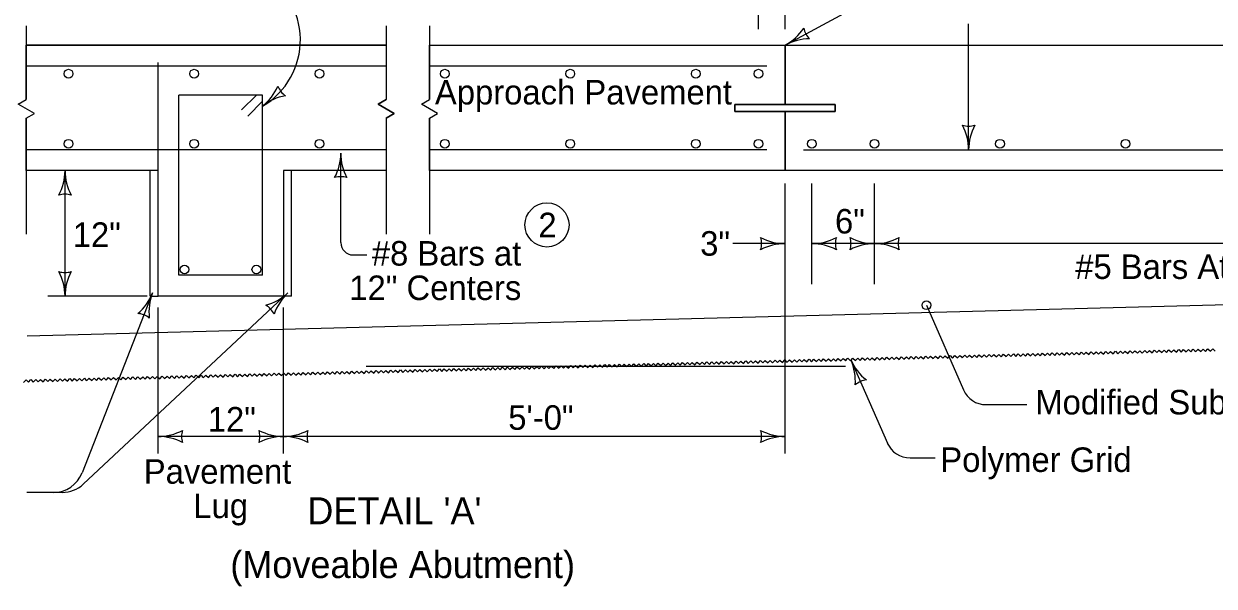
# Model space of a CAD drawing. Extents: x 8925 to 81668, y 4369 to 11918.
# Drawn here: x 11330 to 12301, y 9119 to 9577 of the extents above; entities that cross this region are included whole.
import ezdxf

# ---------------------------------------------------------------- set-up
doc = ezdxf.new("R2010")
doc.units = 0
for name, color, linetype in [('dsnShtPlotShapeBatchPrint', 7, 'Continuous'), ('dsnStdBorder', 7, 'Continuous'), ('Level 2', 7, 'Continuous'), ('Level 3', 7, 'Continuous'), ('Level 5', 7, 'Continuous')]:
    doc.layers.add(name, color=color, linetype=linetype)

msp = doc.modelspace()

# ---------------------------------------------------------------- linework, layer by layer
at = {"layer": 'dsnShtPlotShapeBatchPrint'}
for p, q in [((11950.96, 9572.8), (11950.96, 9732.01)), ((11950.96, 9559.76), (12114.15, 9648.09)), ((11929.18, 9572.8), (11929.18, 9623.99)), ((12100.63, 9474.5), (12100.63, 9577.16)), ((12100.63, 9474.5), (12100.63, 9577.16)), ((11331.99, 9515.32), (11331.99, 9559.76)), ((11331.99, 9559.76), (11625.42, 9559.76)), ((11625.42, 9559.76), (11625.42, 9515.32)), ((11660.94, 9515.32), (11660.94, 9559.76)), ((11660.94, 9559.76), (11950.96, 9559.76)), ((11660.94, 9559.76), (11950.96, 9559.76)), ((11950.96, 9559.76), (11950.96, 9511.44)), ((11950.96, 9511.44), (11950.96, 9559.76)), ((11950.96, 9559.76), (12427.36, 9559.76)), ((11950.96, 9559.76), (12427.36, 9559.76)), ((11950.96, 9511.44), (11950.96, 9559.76)), ((11439.44, 9382.79), (11439.44, 9545.73)), ((11660.94, 9515.32), (11660.94, 9515.32)), ((11950.96, 9511.44), (11910.04, 9511.45)), ((11910.04, 9511.45), (11910.04, 9505.76)), ((11910.04, 9511.45), (11910.04, 9505.77)), ((11910.04, 9505.77), (11950.96, 9505.76)), ((11991.89, 9505.76), (11910.04, 9505.76)), ((11991.88, 9511.45), (11950.96, 9511.44)), ((11950.96, 9505.76), (11991.88, 9505.77)), ((11950.96, 9505.76), (11950.96, 9457.45)), ((11950.96, 9457.45), (11950.96, 9505.76)), ((11950.96, 9457.45), (11950.96, 9505.76)), ((11991.88, 9505.77), (11991.88, 9511.45)), ((11991.89, 9505.76), (11991.89, 9511.45)), ((11331.99, 9457.45), (11331.99, 9500.16)), ((11625.42, 9500.15), (11625.42, 9457.45)), ((11660.94, 9457.45), (11660.94, 9500.15)), ((11588.49, 9398.83), (11588.49, 9471.72)), ((11439.44, 9457.45), (11331.99, 9457.45)), ((11363.58, 9355.15), (11363.58, 9457.45)), ((11439.44, 9355.15), (11439.44, 9457.45)), ((11541.74, 9457.46), (11541.74, 9355.15)), ((11625.42, 9457.45), (11541.74, 9457.45)), ((11541.74, 9457.45), (11541.74, 9355.15)), ((11950.96, 9457.45), (11660.94, 9457.45)), ((11950.96, 9457.45), (11660.94, 9457.45)), ((12427.36, 9457.45), (11950.96, 9457.45)), ((12427.36, 9457.45), (11950.96, 9457.45)), ((11950.96, 9226.93), (11950.96, 9446.96)), ((11972.75, 9364.95), (11972.75, 9446.96)), ((12023.9, 9364.95), (12023.9, 9446.96)), ((11950.96, 9397.95), (11908.33, 9397.95)), ((12023.9, 9397.95), (11972.75, 9397.95)), ((12846.66, 9397.95), (12023.9, 9397.95)), ((11598.59, 9388.72), (11609.85, 9388.72)), ((11332.73, 9322.65), (12427.72, 9351.24)), ((11430.46, 9355.15), (11349.66, 9355.15)), ((11434.98, 9357.74), (11377.44, 9210.94)), ((11545.34, 9357.74), (11378.42, 9201.79)), ((11541.74, 9355.15), (11439.44, 9355.15)), ((11439.44, 9226.93), (11439.44, 9345.73)), ((11541.74, 9226.93), (11541.74, 9345.73)), ((12066.16, 9347.65), (12096.31, 9278.76)), ((12004.65, 9303.08), (12034.31, 9235.33)), ((12114.83, 9266.66), (12148.21, 9266.66)), ((11541.74, 9240.71), (11439.44, 9240.71)), ((11950.96, 9240.71), (11541.74, 9240.71)), ((12052.82, 9223.23), (12073.33, 9223.23)), ((11361.35, 9195.06), (11332.39, 9195.06))]:
    msp.add_line(p, q, dxfattribs=at)
for points in [[(11331.99, 9500.16), (11338.56, 9503.94), (11325.42, 9511.53), (11331.99, 9515.32)], [(11625.42, 9515.32), (11618.86, 9511.53), (11631.99, 9503.94), (11625.42, 9500.16)], [(11660.94, 9500.16), (11667.51, 9503.94), (11654.37, 9511.53), (11660.94, 9515.32)], [(12237.29, 9309.59), (12238.31, 9308.62), (12240.24, 9310.66), (12242.28, 9308.73), (12244.21, 9310.76), (12246.24, 9308.83), (12248.18, 9310.87), (12250.21, 9308.94), (12252.15, 9310.97), (12254.18, 9309.04), (12256.11, 9311.07), (12258.15, 9309.14), (12260.08, 9311.18), (12262.11, 9309.24), (12264.05, 9311.28), (12266.08, 9309.35), (12268.01, 9311.39), (12270.05, 9309.45), (12271.98, 9311.49), (12274.02, 9309.56), (12275.95, 9311.59), (12277.98, 9309.66), (12279.92, 9311.69), (12281.95, 9309.77), (12283.88, 9311.8), (12284.9, 9310.83)], [(12284.9, 9310.83), (12285.92, 9309.87), (12287.85, 9311.9), (12289.89, 9309.97), (12291.82, 9312.01), (12293.86, 9310.08), (12295.79, 9312.11), (12297.82, 9310.18), (12299.75, 9312.21), (12301.79, 9310.28)], [(11856.43, 9299.64), (11857.44, 9298.68), (11859.38, 9300.71), (11861.41, 9298.78), (11863.34, 9300.82), (11865.38, 9298.88), (11867.31, 9300.92), (11869.35, 9298.99), (11871.28, 9301.02), (11873.32, 9299.09), (11875.24, 9301.13), (11877.28, 9299.2), (11879.21, 9301.23), (11881.25, 9299.3), (11883.18, 9301.33), (11885.22, 9299.41), (11887.15, 9301.44), (11889.18, 9299.51), (11891.11, 9301.54), (11893.15, 9299.61), (11895.08, 9301.64), (11897.12, 9299.71), (11899.05, 9301.75), (11901.09, 9299.82), (11903.02, 9301.85), (11904.04, 9300.89)], [(11904.04, 9300.89), (11905.05, 9299.92), (11906.99, 9301.96), (11909.02, 9300.02), (11910.95, 9302.06), (11912.98, 9300.13), (11914.92, 9302.16), (11916.95, 9300.23), (11918.89, 9302.27), (11920.92, 9300.34), (11922.85, 9302.37), (11924.89, 9300.44), (11926.82, 9302.47), (11928.86, 9300.55), (11930.79, 9302.58), (11932.82, 9300.65), (11934.75, 9302.68), (11936.79, 9300.75), (11938.72, 9302.78), (11940.76, 9300.85), (11942.69, 9302.89), (11944.73, 9300.96), (11946.66, 9302.99), (11948.69, 9301.06), (11950.63, 9303.09), (11951.64, 9302.13)], [(11951.64, 9302.13), (11952.66, 9301.16), (11954.59, 9303.2), (11956.63, 9301.27), (11958.56, 9303.3), (11960.6, 9301.37), (11962.53, 9303.41), (11964.56, 9301.48), (11966.5, 9303.51), (11968.53, 9301.58), (11970.46, 9303.61), (11972.5, 9301.68), (11974.43, 9303.72), (11976.46, 9301.79), (11978.4, 9303.82), (11980.43, 9301.89), (11982.36, 9303.92), (11984.4, 9301.99), (11986.33, 9304.03), (11988.37, 9302.1), (11990.3, 9304.13), (11992.33, 9302.2), (11994.27, 9304.23), (11996.3, 9302.3), (11998.23, 9304.34), (11999.25, 9303.38)], [(11999.25, 9303.38), (12000.27, 9302.41), (12002.2, 9304.44), (12004.24, 9302.51), (12006.17, 9304.55), (12008.21, 9302.62), (12010.14, 9304.65), (12012.17, 9302.72), (12014.1, 9304.75), (12016.14, 9302.82), (12018.07, 9304.85), (12020.11, 9302.93), (12022.04, 9304.96), (12024.07, 9303.03), (12026.01, 9305.06), (12028.04, 9303.13), (12029.97, 9305.16), (12032.01, 9303.24), (12033.94, 9305.27), (12035.98, 9303.34), (12037.91, 9305.37), (12039.94, 9303.44), (12041.87, 9305.48), (12043.91, 9303.54), (12045.84, 9305.58), (12046.86, 9304.61)], [(12046.86, 9304.61), (12047.88, 9303.65), (12049.81, 9305.69), (12051.84, 9303.75), (12053.78, 9305.79), (12055.81, 9303.86), (12057.74, 9305.89), (12059.78, 9303.96), (12061.71, 9305.99), (12063.75, 9304.07), (12065.68, 9306.1), (12067.72, 9304.17), (12069.65, 9306.2), (12071.68, 9304.27), (12073.62, 9306.3), (12075.65, 9304.38), (12077.58, 9306.41), (12079.62, 9304.48), (12081.55, 9306.51), (12083.58, 9304.58), (12085.52, 9306.62), (12087.55, 9304.68), (12089.48, 9306.72), (12091.52, 9304.79), (12093.45, 9306.83), (12094.47, 9305.86)], [(12094.47, 9305.86), (12095.48, 9304.89), (12097.42, 9306.93), (12099.45, 9305), (12101.38, 9307.03), (12103.42, 9305.1), (12105.35, 9307.13), (12107.38, 9305.2), (12109.32, 9307.24), (12111.36, 9305.31), (12113.29, 9307.34), (12115.32, 9305.41), (12117.25, 9307.45), (12119.29, 9305.52), (12121.22, 9307.55), (12123.26, 9305.62), (12125.19, 9307.65), (12127.23, 9305.72), (12129.16, 9307.76), (12131.19, 9305.82), (12133.13, 9307.86), (12135.16, 9305.93), (12137.09, 9307.97), (12139.12, 9306.03), (12141.06, 9308.07), (12142.07, 9307.1)], [(12142.07, 9307.1), (12143.09, 9306.14), (12145.03, 9308.17), (12147.06, 9306.24), (12148.99, 9308.27), (12151.03, 9306.34), (12152.96, 9308.38), (12155, 9306.45), (12156.93, 9308.48), (12158.96, 9306.55), (12160.9, 9308.59), (12162.93, 9306.66), (12164.86, 9308.68), (12166.9, 9306.76), (12168.83, 9308.79), (12170.87, 9306.86), (12172.79, 9308.9), (12174.83, 9306.96), (12176.76, 9309), (12178.8, 9307.07), (12180.73, 9309.11), (12182.77, 9307.17), (12184.7, 9309.21), (12186.74, 9307.28), (12188.67, 9309.31), (12189.69, 9308.35)], [(12189.69, 9308.35), (12190.7, 9307.38), (12192.64, 9309.41), (12194.67, 9307.48), (12196.6, 9309.52), (12198.64, 9307.59), (12200.57, 9309.62), (12202.6, 9307.69), (12204.53, 9309.73), (12206.57, 9307.8), (12208.5, 9309.83), (12210.54, 9307.9), (12212.47, 9309.93), (12214.51, 9308.01), (12216.44, 9310.04), (12218.47, 9308.1), (12220.4, 9310.14), (12222.44, 9308.21), (12224.37, 9310.25), (12226.41, 9308.31), (12228.34, 9310.35), (12230.38, 9308.42), (12232.31, 9310.45), (12234.34, 9308.52), (12236.28, 9310.55), (12237.29, 9309.59)], [(11523.17, 9290.94), (11524.19, 9289.97), (11526.11, 9292.01), (11528.15, 9290.08), (11530.09, 9292.11), (11532.12, 9290.18), (11534.05, 9292.22), (11536.09, 9290.29), (11538.02, 9292.32), (11540.05, 9290.39), (11541.99, 9292.42), (11544.02, 9290.49), (11545.96, 9292.53), (11547.99, 9290.6), (11549.92, 9292.63), (11551.96, 9290.7), (11553.89, 9292.73), (11555.93, 9290.81), (11557.86, 9292.83), (11559.89, 9290.91), (11561.83, 9292.94), (11563.86, 9291.01), (11565.79, 9293.05), (11567.83, 9291.11), (11569.76, 9293.15), (11570.78, 9292.18)], [(11570.78, 9292.18), (11571.79, 9291.22), (11573.73, 9293.25), (11575.76, 9291.32), (11577.69, 9293.36), (11579.73, 9291.42), (11581.66, 9293.46), (11583.7, 9291.53), (11585.63, 9293.56), (11587.67, 9291.63), (11589.6, 9293.67), (11591.63, 9291.73), (11593.56, 9293.77), (11595.6, 9291.84), (11597.53, 9293.87), (11599.57, 9291.95), (11601.5, 9293.97), (11603.53, 9292.05), (11605.46, 9294.08), (11607.5, 9292.15), (11609.43, 9294.18), (11611.47, 9292.25), (11613.4, 9294.29), (11615.44, 9292.36), (11617.37, 9294.39), (11618.39, 9293.42)], [(11618.39, 9293.42), (11619.4, 9292.46), (11621.34, 9294.49), (11623.37, 9292.56), (11625.31, 9294.6), (11627.34, 9292.67), (11629.27, 9294.7), (11631.3, 9292.77), (11633.24, 9294.81), (11635.27, 9292.87), (11637.2, 9294.91), (11639.24, 9292.98), (11641.17, 9295.01), (11643.21, 9293.08), (11645.14, 9295.11), (11647.18, 9293.19), (11649.1, 9295.22), (11651.14, 9293.29), (11653.07, 9295.32), (11655.11, 9293.39), (11657.04, 9295.43), (11659.08, 9293.5), (11661.01, 9295.53), (11663.04, 9293.6), (11664.98, 9295.63), (11666, 9294.67)], [(11666, 9294.67), (11667.01, 9293.71), (11668.94, 9295.74), (11670.98, 9293.81), (11672.91, 9295.84), (11674.95, 9293.91), (11676.88, 9295.95), (11678.91, 9294.01), (11680.85, 9296.05), (11682.88, 9294.12), (11684.82, 9296.16), (11686.85, 9294.22), (11688.78, 9296.25), (11690.81, 9294.33), (11692.75, 9296.36), (11694.78, 9294.43), (11696.71, 9296.46), (11698.75, 9294.53), (11700.68, 9296.57), (11702.72, 9294.64), (11704.65, 9296.67), (11706.68, 9294.74), (11708.61, 9296.77), (11710.65, 9294.85), (11712.59, 9296.88), (11713.6, 9295.91)], [(11713.6, 9295.91), (11714.62, 9294.95), (11716.55, 9296.98), (11718.59, 9295.05), (11720.52, 9297.09), (11722.56, 9295.15), (11724.49, 9297.19), (11726.52, 9295.26), (11728.46, 9297.3), (11730.49, 9295.36), (11732.42, 9297.39), (11734.46, 9295.47), (11736.39, 9297.5), (11738.42, 9295.57), (11740.36, 9297.6), (11742.39, 9295.67), (11744.32, 9297.71), (11746.36, 9295.78), (11748.29, 9297.81), (11750.33, 9295.88), (11752.26, 9297.91), (11754.29, 9295.99), (11756.22, 9298.01), (11758.26, 9296.09), (11760.19, 9298.12), (11761.21, 9297.15)], [(11761.21, 9297.15), (11762.23, 9296.19), (11764.16, 9298.23), (11766.2, 9296.29), (11768.13, 9298.33), (11770.16, 9296.4), (11772.09, 9298.43), (11774.13, 9296.5), (11776.06, 9298.53), (11778.1, 9296.61), (11780.03, 9298.64), (11782.07, 9296.71), (11784, 9298.74), (11786.03, 9296.81), (11787.97, 9298.85), (11790, 9296.92), (11791.93, 9298.95), (11793.96, 9297.02), (11795.9, 9299.05), (11797.93, 9297.13), (11799.87, 9299.16), (11801.9, 9297.23), (11803.84, 9299.26), (11805.87, 9297.33), (11807.8, 9299.37), (11808.82, 9298.4)], [(11808.82, 9298.4), (11809.83, 9297.43), (11811.76, 9299.47), (11813.81, 9297.54), (11815.74, 9299.57), (11817.77, 9297.64), (11819.7, 9299.68), (11821.74, 9297.75), (11823.67, 9299.78), (11825.71, 9297.85), (11827.64, 9299.88), (11829.67, 9297.95), (11831.6, 9299.99), (11833.64, 9298.06), (11835.57, 9300.09), (11837.61, 9298.16), (11839.54, 9300.19), (11841.58, 9298.27), (11843.51, 9300.3), (11845.54, 9298.37), (11847.48, 9300.4), (11849.51, 9298.47), (11851.44, 9300.51), (11853.47, 9298.57), (11855.41, 9300.61), (11856.43, 9299.64)], [(11332.96, 9285.84), (11331.85, 9286.9), (11329.72, 9284.67)], [(11332.74, 9285.96), (11333.76, 9285), (11335.68, 9287.04), (11337.72, 9285.11), (11339.66, 9287.14), (11341.69, 9285.21), (11343.62, 9287.24), (11345.65, 9285.31), (11347.59, 9287.34), (11349.62, 9285.42), (11351.56, 9287.45), (11353.59, 9285.52), (11355.52, 9287.56), (11357.56, 9285.62), (11359.49, 9287.66), (11361.53, 9285.73), (11363.46, 9287.76), (11365.49, 9285.83), (11367.42, 9287.86), (11369.46, 9285.93), (11371.39, 9287.97), (11373.42, 9286.04), (11375.36, 9288.07), (11377.4, 9286.14), (11379.33, 9288.17), (11380.34, 9287.21)], [(11380.34, 9287.21), (11381.36, 9286.25), (11383.29, 9288.28), (11385.33, 9286.35), (11387.26, 9288.38), (11389.3, 9286.45), (11391.23, 9288.48), (11393.27, 9286.56), (11395.2, 9288.59), (11397.23, 9286.66), (11399.17, 9288.7), (11401.2, 9286.76), (11403.13, 9288.8), (11405.16, 9286.87), (11407.1, 9288.9), (11409.13, 9286.97), (11411.06, 9289), (11413.1, 9287.07), (11415.03, 9289.11), (11417.07, 9287.18), (11419, 9289.21), (11421.04, 9287.28), (11422.96, 9289.31), (11425, 9287.39), (11426.94, 9289.42), (11427.95, 9288.45)], [(11427.95, 9288.45), (11428.97, 9287.49), (11430.9, 9289.52), (11432.94, 9287.59), (11434.87, 9289.63), (11436.91, 9287.69), (11438.84, 9289.73), (11440.87, 9287.8), (11442.8, 9289.84), (11444.84, 9287.9), (11446.77, 9289.94), (11448.81, 9288.01), (11450.74, 9290.04), (11452.77, 9288.11), (11454.71, 9290.14), (11456.74, 9288.21), (11458.68, 9290.25), (11460.71, 9288.32), (11462.64, 9290.35), (11464.68, 9288.42), (11466.61, 9290.45), (11468.64, 9288.53), (11470.57, 9290.56), (11472.61, 9288.63), (11474.54, 9290.66), (11475.56, 9289.7)], [(11475.56, 9289.7), (11476.58, 9288.73), (11478.51, 9290.77), (11480.55, 9288.83), (11482.48, 9290.87), (11484.51, 9288.94), (11486.44, 9290.97), (11488.48, 9289.04), (11490.41, 9291.08), (11492.45, 9289.15), (11494.38, 9291.18), (11496.41, 9289.25), (11498.35, 9291.28), (11500.38, 9289.35), (11502.32, 9291.39), (11504.35, 9289.45), (11506.28, 9291.49), (11508.32, 9289.56), (11510.25, 9291.59), (11512.28, 9289.67), (11514.22, 9291.7), (11516.25, 9289.77), (11518.18, 9291.8), (11520.22, 9289.87), (11522.15, 9291.91), (11523.17, 9290.94)]]:
    msp.add_lwpolyline(points, dxfattribs=at)
for centre, radius, start, end in [((11492.57, 9564.1), 62.96, 300.6735, 60.83314), ((11598.59, 9398.83), 10.1, 180, 270), ((12114.83, 9286.86), 20.21, 203.64012, 270), ((12052.82, 9243.44), 20.21, 203.64012, 270)]:
    msp.add_arc(centre, radius, start, end, dxfattribs=at)
at = {"layer": 'dsnStdBorder'}
for p, q in [((11331.99, 9575.4), (11331.99, 9515.32)), ((11625.42, 9575.4), (11625.42, 9515.32)), ((11660.94, 9575.4), (11660.94, 9515.32)), ((11625.42, 9559.76), (11331.99, 9559.76)), ((11950.96, 9511.44), (11950.96, 9559.76)), ((11625.42, 9542.71), (11331.99, 9542.71)), ((11935.9, 9542.71), (11660.94, 9542.71)), ((11456.49, 9372.2), (11456.49, 9518.95)), ((11524.69, 9518.95), (11456.49, 9518.95)), ((11519.71, 9518.95), (11507.65, 9506.89)), ((11524.69, 9372.2), (11524.69, 9518.95)), ((11524.69, 9513.96), (11512.63, 9501.91)), ((11910.04, 9505.76), (11910.04, 9511.45)), ((11910.04, 9511.45), (11991.89, 9511.45)), ((11991.89, 9505.76), (11910.04, 9505.76)), ((11950.96, 9457.45), (11950.96, 9505.76)), ((11991.89, 9511.45), (11991.89, 9505.76)), ((11331.99, 9500.15), (11331.99, 9405.54)), ((11625.42, 9500.15), (11625.42, 9405.54)), ((11660.94, 9500.15), (11660.94, 9405.54)), ((11625.42, 9474.5), (11331.99, 9474.5)), ((11935.9, 9474.5), (11660.94, 9474.5)), ((11966.03, 9474.5), (12427.36, 9474.5)), ((11439.44, 9457.45), (11331.99, 9457.45)), ((11432.97, 9355.15), (11432.97, 9457.46)), ((11439.44, 9355.15), (11439.44, 9457.46)), ((11625.42, 9457.45), (11541.74, 9457.45)), ((11548.21, 9355.15), (11548.21, 9457.46)), ((11524.69, 9372.2), (11456.49, 9372.2)), ((11432.97, 9355.15), (11439.44, 9355.15)), ((11541.74, 9355.15), (11439.44, 9355.15)), ((11548.21, 9355.15), (11541.74, 9355.15)), ((11609.2, 9297.99), (12000.11, 9297.99))]:
    msp.add_line(p, q, dxfattribs=at)
for points in [[(11331.99, 9500.16), (11338.56, 9503.94), (11325.42, 9511.53), (11331.99, 9515.32)], [(11625.42, 9500.16), (11631.99, 9503.94), (11618.86, 9511.53), (11625.42, 9515.32)], [(11660.94, 9500.16), (11667.51, 9503.94), (11654.37, 9511.53), (11660.94, 9515.32)]]:
    msp.add_lwpolyline(points, dxfattribs=at)
msp.add_circle((11756.7, 9413.16), 18, dxfattribs=at)
for centre, radius, start, end in [((11498.13, 9543.14), 42.5, 308.6676, 336.74009), ((11552.51, 9532.22), 16.42, 200.93424, 236.40095), ((11551.24, 9476.77), 42.5, 100.59511, 128.6676), ((11354.16, 9220.06), 25, 270, 338.59752), ((11361.35, 9220.06), 25, 270, 313.05415)]:
    msp.add_arc(centre, radius, start, end, dxfattribs=at)
at = {"layer": 'Level 2'}
for centre in [(11366.5, 9536.5), (11468.81, 9536.5), (11571.11, 9536.5), (11673.42, 9536.5), (11775.72, 9536.5), (11878.03, 9536.5), (11929.18, 9536.5), (11366.5, 9479.4), (11468.81, 9479.4), (11571.11, 9479.4), (11673.42, 9479.4), (11775.72, 9479.4), (11878.03, 9479.4), (11929.18, 9479.4), (11972.75, 9479.4), (12023.9, 9479.4), (12126.2, 9479.4), (12228.51, 9479.4), (11461.09, 9376.82), (11519.63, 9376.82)]:
    msp.add_circle(centre, 3.55, dxfattribs=at)
at = {"layer": 'Level 3'}
for centre, radius, start, end in [((11930.73, 9597.13), 42.5, 298.42581, 326.4983), ((11982.3, 9576.72), 16.42, 190.69246, 226.15916), ((11971.19, 9522.38), 42.5, 90.35332, 118.42581), ((12100.63, 9510.14), 16.42, 252.26665, 287.73335), ((12058.13, 9474.5), 42.5, 360, 28.07249), ((12143.13, 9474.5), 42.5, 151.92751, 180), ((11545.99, 9471.72), 42.5, 331.92751, 360), ((11630.99, 9471.72), 42.5, 180, 208.07249), ((11321.08, 9457.45), 42.5, 331.92751, 360), ((11406.08, 9457.45), 42.5, 180, 208.07249), ((11588.49, 9436.08), 16.42, 72.26665, 107.73335), ((11363.58, 9421.82), 16.42, 72.26665, 107.73335), ((11915.33, 9397.95), 16.42, 342.26665, 17.73335), ((11950.96, 9440.45), 42.5, 241.92751, 270), ((11972.75, 9440.45), 42.5, 270, 298.07249), ((12008.38, 9397.95), 16.42, 162.26665, 197.73335), ((11988.26, 9397.95), 16.42, 342.26665, 17.73335), ((12023.9, 9440.45), 42.5, 241.92751, 270), ((12023.9, 9440.45), 42.5, 270, 298.07249), ((12059.53, 9397.95), 16.42, 162.26665, 197.73335), ((11950.96, 9355.45), 42.5, 90, 118.07249), ((11972.75, 9355.45), 42.5, 61.92751, 90), ((12023.9, 9355.45), 42.5, 90, 118.07249), ((12023.9, 9355.45), 42.5, 61.92751, 90), ((11363.58, 9390.78), 16.42, 252.26665, 287.73335), ((11321.08, 9355.15), 42.5, 360, 28.07249), ((11406.08, 9355.15), 42.5, 151.92751, 180), ((11395.41, 9373.25), 42.5, 310.52503, 338.59752), ((11474.55, 9342.23), 42.5, 158.59752, 186.67), ((11516.32, 9388.8), 42.5, 284.98166, 313.05415), ((11574.35, 9326.69), 42.5, 133.05415, 161.12664), ((11421.97, 9324.56), 16.42, 50.86416, 86.33087), ((11519.3, 9333.41), 16.42, 25.3208, 60.7875), ((12043.59, 9320.12), 42.5, 203.64012, 231.71261), ((11965.72, 9286.04), 42.5, 355.56763, 23.64012), ((12018.94, 9270.44), 16.42, 95.90677, 131.37347), ((11439.44, 9283.21), 42.5, 270, 298.07249), ((11475.07, 9240.71), 16.42, 162.26665, 197.73335), ((11506.11, 9240.71), 16.42, 342.26665, 17.73335), ((11541.74, 9283.21), 42.5, 241.92751, 270), ((11541.74, 9283.21), 42.5, 270, 298.07249), ((11577.38, 9240.71), 16.42, 162.26665, 197.73335), ((11915.33, 9240.71), 16.42, 342.26665, 17.73335), ((11950.96, 9283.21), 42.5, 241.92751, 270), ((11439.44, 9198.21), 42.5, 61.92751, 90), ((11541.74, 9198.21), 42.5, 90, 118.07249), ((11541.74, 9198.21), 42.5, 61.92751, 90), ((11950.96, 9198.21), 42.5, 90, 118.07249)]:
    msp.add_arc(centre, radius, start, end, dxfattribs=at)
at = {"layer": 'Level 5'}
msp.add_circle((12066.16, 9347.65), 3.54, dxfattribs=at)

# ---------------------------------------------------------------- texts
at = {"layer": 'dsnShtPlotShapeBatchPrint'}
for s, height, p in [('Approach Pavement', 20, (11665.28, 9511.39)), ('2', 20, (11749.68, 9403.16)), ('6"', 20, (11991.63, 9406.2)), ('12"', 20, (11369.86, 9395.26)), ('#8 Bars at', 20, (11613.83, 9380.03)), ('3"', 20, (11881.65, 9388.1)), ('#5 Bars At 12" max. Centers', 20, (12187.56, 9369.14)), ('12" Centers', 20, (11595.44, 9351.94)), ('Modified Subbase', 20, (12155, 9258.67)), ('12"', 20, (11480.01, 9244.74)), ('5\'-0"', 20, (11725.1, 9246.15)), ('Polymer Grid', 20, (12077.52, 9211.78)), ('Pavement', 20, (11427.81, 9202.2)), ('Lug', 20, (11468.23, 9174.11)), ('(Moveable Abutment)', 22, (11498.36, 9125.27))]:
    msp.add_text(s, height=height, dxfattribs=at).set_placement(p)
at = {"layer": 'dsnStdBorder'}
msp.add_text("DETAIL 'A' ", height=22, dxfattribs=at).set_placement((11561.19, 9169.13))

doc.saveas('drawing.dxf')
